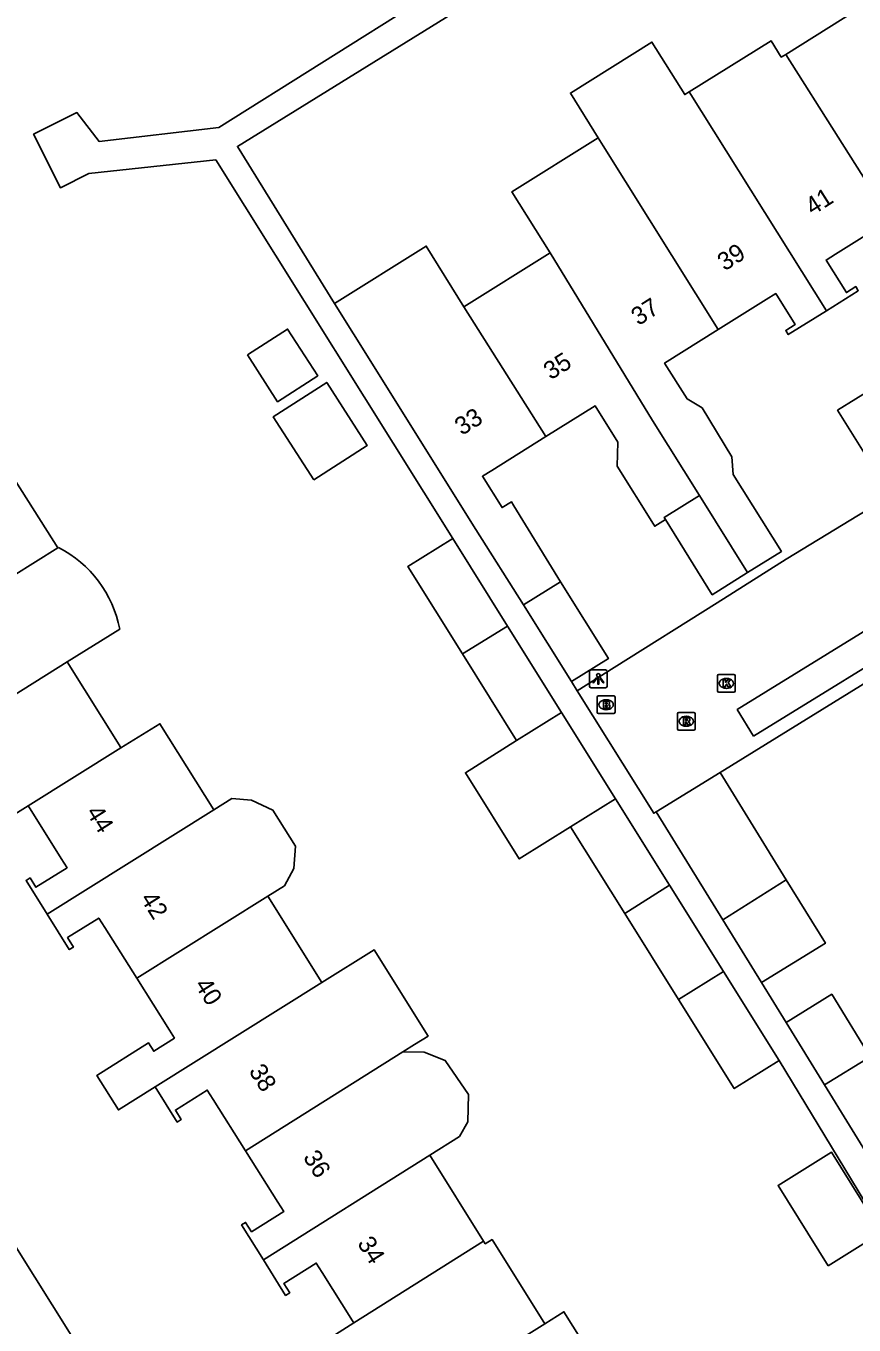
# Model space of a CAD drawing. Extents: x 157767 to 159171, y 387842 to 389425.
# Drawn here: x 158300.1 to 158346.5, y 388151.6 to 388224.4 of the extents above; entities that cross this region are included whole.
import ezdxf

# ---------------------------------------------------------------- set-up
doc = ezdxf.new("R2010")
doc.units = 0
for name, color, linetype in [('IMGEO_Brandkraan', 7, 'Continuous'), ('IMGEO_Kolk', 7, 'Continuous'), ('IMGEO_Lichtpunt', 7, 'Continuous'), ('IMGEO_Muur', 7, 'Continuous'), ('IMGEO_Pand', 7, 'Continuous'), ('IMGEO_Pand_nummerreeks', 7, 'Continuous'), ('IMGEO_Rijbaan_lokaal_open', 7, 'Continuous'), ('IMGEO_Rioolput', 7, 'Continuous'), ('IMGEO_Voetpad_open', 7, 'Continuous')]:
    doc.layers.add(name, color=color, linetype=linetype)

msp = doc.modelspace()

# ---------------------------------------------------------------- linework, layer by layer
at = {"layer": 'IMGEO_Brandkraan'}
for p, q in [((158332.146, 388185.961), (158332.146, 388186.813)), ((158332.221, 388186.887), (158333.073, 388186.887)), ((158332.634, 388186.667), (158332.659, 388186.667)), ((158333.147, 388186.813), (158333.147, 388185.961)), ((158333.073, 388185.887), (158332.221, 388185.887)), ((158332.657, 388186.107), (158332.632, 388186.107))]:
    msp.add_line(p, q, dxfattribs=at)
for points in [[(158332.146, 388185.961), (158332.146, 388186.813)], [(158332.221, 388186.887), (158333.073, 388186.887)], [(158332.494, 388186.587), (158332.494, 388186.187), (158332.707, 388186.187)], [(158332.725, 388186.587), (158332.494, 388186.587)], [(158332.673, 388186.506), (158332.619, 388186.506), (158332.619, 388186.43)], [(158332.619, 388186.43), (158332.672, 388186.43)], [(158332.681, 388186.354), (158332.619, 388186.354), (158332.619, 388186.273)], [(158333.147, 388186.813), (158333.147, 388185.961)], [(158333.073, 388185.887), (158332.221, 388185.887)], [(158332.619, 388186.273), (158332.681, 388186.273)]]:
    msp.add_lwpolyline(points, dxfattribs=at)
for centre, radius, start, end in [((158332.223, 388186.811), 0.0765, 91.55205, 178.44795), ((158332.223, 388186.811), 0.0765, 91.55205, 178.44795), ((158332.674, 388186.468), 0.0379, 267.82845, 90.93552), ((158332.682, 388186.313), 0.0404, 269.87594, 90.50774), ((158332.729, 388186.442), 0.145, 59.4692, 91.53667), ((158332.754, 388186.489), 0.0922, 285.51372, 58.15012), ((158332.759, 388186.297), 0.105, 301.31148, 78.98903), ((158333.071, 388186.811), 0.0765, 1.55205, 88.44795), ((158333.071, 388186.811), 0.0765, 1.55205, 88.44795), ((158332.223, 388185.963), 0.0765, 181.55205, 268.44795), ((158332.223, 388185.963), 0.0765, 181.55205, 268.44795), ((158332.713, 388186.438), 0.251, 268.66757, 293.53466), ((158333.071, 388185.963), 0.0765, 271.55205, 358.44795), ((158333.071, 388185.963), 0.0765, 271.55205, 358.44795)]:
    msp.add_arc(centre, radius, start, end, dxfattribs=at)
for centre, major_axis, ratio, start_param, end_param in [((158332.633, 388186.387), (-0.387, 0.002), 0.722429, 4.712389, 7.853982), ((158332.658, 388186.387), (-0.39, 0.002), 0.717154, 1.570796, 4.712389)]:
    msp.add_ellipse(centre, major_axis=major_axis, ratio=ratio, start_param=start_param, end_param=end_param, dxfattribs=at)
at = {"layer": 'IMGEO_Kolk'}
for p, q in [((158338.887, 388187.156), (158338.887, 388188.008)), ((158338.962, 388188.082), (158339.814, 388188.082)), ((158339.375, 388187.862), (158339.4, 388187.862)), ((158339.888, 388188.008), (158339.888, 388187.156)), ((158339.814, 388187.082), (158338.962, 388187.082)), ((158339.398, 388187.302), (158339.373, 388187.302))]:
    msp.add_line(p, q, dxfattribs=at)
for points in [[(158338.887, 388187.156), (158338.887, 388188.008)], [(158338.962, 388188.082), (158339.814, 388188.082)], [(158339.208, 388187.782), (158339.331, 388187.782), (158339.331, 388187.631), (158339.461, 388187.782), (158339.625, 388187.782), (158339.479, 388187.631), (158339.632, 388187.382), (158339.48, 388187.382), (158339.395, 388187.546), (158339.331, 388187.479), (158339.331, 388187.382), (158339.208, 388187.382), (158339.208, 388187.782)], [(158339.888, 388188.008), (158339.888, 388187.156)], [(158339.814, 388187.082), (158338.962, 388187.082)]]:
    msp.add_lwpolyline(points, dxfattribs=at)
for centre, start, end in [((158338.964, 388188.006), 91.55205, 178.44795), ((158338.964, 388188.006), 91.55205, 178.44795), ((158339.812, 388188.006), 1.55205, 88.44795), ((158339.812, 388188.006), 1.55205, 88.44795), ((158338.964, 388187.158), 181.55205, 268.44795), ((158338.964, 388187.158), 181.55205, 268.44795), ((158339.812, 388187.158), 271.55205, 358.44795), ((158339.812, 388187.158), 271.55205, 358.44795)]:
    msp.add_arc(centre, 0.0765, start, end, dxfattribs=at)
for centre, major_axis, ratio, start_param, end_param in [((158339.374, 388187.582), (-0.387, 0.002), 0.722429, 4.712389, 7.853982), ((158339.399, 388187.582), (-0.39, 0.002), 0.717154, 1.570796, 4.712389)]:
    msp.add_ellipse(centre, major_axis=major_axis, ratio=ratio, start_param=start_param, end_param=end_param, dxfattribs=at)
at = {"layer": 'IMGEO_Lichtpunt'}
for p, q in [((158331.71, 388188.236), (158331.71, 388187.429)), ((158331.71, 388188.236), (158331.71, 388187.429)), ((158332.612, 388188.331), (158331.804, 388188.331)), ((158332.612, 388188.331), (158331.804, 388188.331)), ((158332.706, 388187.429), (158332.706, 388188.236)), ((158332.706, 388187.429), (158332.706, 388188.236)), ((158331.804, 388187.335), (158332.612, 388187.335)), ((158331.804, 388187.335), (158332.612, 388187.335))]:
    msp.add_line(p, q, dxfattribs=at)
for points in [[(158332.084, 388187.9), (158332.123, 388187.872), (158331.935, 388187.61), (158331.897, 388187.637), (158332.084, 388187.9)], [(158332.186, 388187.852), (158332.233, 388187.852), (158332.233, 388187.53), (158332.186, 388187.53), (158332.186, 388187.852)], [(158332.296, 388187.872), (158332.334, 388187.899), (158332.521, 388187.637), (158332.482, 388187.609), (158332.296, 388187.872)]]:
    msp.add_lwpolyline(points, dxfattribs=at)
msp.add_circle((158332.209, 388188.034), 0.0994, dxfattribs=at)
for centre, start, end in [((158331.804, 388188.236), 90, 180), ((158331.804, 388188.236), 90, 180), ((158332.612, 388188.236), 0, 90), ((158332.612, 388188.236), 0, 90), ((158331.804, 388187.429), 180, 270), ((158331.804, 388187.429), 180, 270), ((158332.612, 388187.429), 270, 0), ((158332.612, 388187.429), 270, 360)]:
    msp.add_arc(centre, 0.0946, start, end, dxfattribs=at)
at = {"layer": 'IMGEO_Muur'}
msp.add_lwpolyline([(158352.615, 388190.965), (158339.034, 388182.597)], dxfattribs=at)
at = {"layer": 'IMGEO_Pand'}
for points in [[(158342.715, 388222.816), (158347.548, 388225.838)], [(158332.203, 388218.146), (158330.642, 388220.645), (158335.214, 388223.501), (158337.058, 388220.56), (158337.309, 388220.717)], [(158337.309, 388220.717), (158341.89, 388223.582), (158342.466, 388222.66), (158342.715, 388222.816)], [(158342.715, 388222.816), (158348.581, 388213.55)], [(158344.993, 388208.458), (158337.309, 388220.717)], [(158329.51, 388211.699), (158327.369, 388215.123), (158332.203, 388218.146)], [(158332.203, 388218.146), (158332.484, 388217.7), (158338.92, 388207.396)], [(158348.581, 388213.55), (158345.5, 388211.624), (158344.976, 388211.296), (158346.113, 388209.477), (158346.638, 388209.805), (158346.781, 388209.576), (158344.993, 388208.458)], [(158317.43, 388208.862), (158322.569, 388212.076), (158324.68, 388208.678)], [(158324.68, 388208.678), (158329.51, 388211.699)], [(158337.882, 388198.105), (158335.252, 388202.31), (158329.51, 388211.699)], [(158344.993, 388208.458), (158342.854, 388207.12), (158342.711, 388207.349), (158343.237, 388207.678), (158342.15, 388209.416), (158341.624, 388209.087), (158338.92, 388207.396)], [(158328.015, 388191.977), (158325.351, 388196.196), (158322.7, 388200.436), (158319.551, 388205.471), (158317.43, 388208.862)], [(158329.261, 388201.403), (158324.68, 388208.678)], [(158312.546, 388205.978), (158314.8, 388207.43), (158316.488, 388204.812), (158314.234, 388203.359), (158312.546, 388205.978)], [(158338.92, 388207.396), (158335.927, 388205.524), (158337.182, 388203.516), (158338.026, 388203.018), (158339.693, 388200.264), (158339.772, 388199.287), (158342.47, 388194.973), (158340.58, 388193.791)], [(158316.261, 388198.98), (158313.991, 388202.504), (158316.989, 388204.436), (158319.259, 388200.912), (158316.261, 388198.98)], [(158350.367, 388199.826), (158348.327, 388198.55), (158345.621, 388202.878), (158347.67, 388204.159)], [(158335.966, 388196.755), (158335.373, 388196.384), (158335.303, 388196.496), (158333.262, 388199.758), (158333.301, 388201.09), (158332.025, 388203.131), (158329.261, 388201.403)], [(158329.261, 388201.403), (158326.24, 388199.514), (158325.715, 388199.186), (158326.814, 388197.429), (158327.339, 388197.757), (158327.482, 388197.528), (158330.086, 388193.272)], [(158298.865, 388200.005), (158301.921, 388195.173)], [(158335.966, 388196.755), (158335.898, 388196.864), (158337.882, 388198.105)], [(158340.58, 388193.791), (158337.882, 388198.105)], [(158340.58, 388193.791), (158338.596, 388192.55), (158335.966, 388196.755)], [(158301.921, 388195.173), (158299.421, 388193.609), (158292.107, 388189.027)], [(158301.921, 388195.173), (158301.957, 388195.196)], [(158324.594, 388189.227), (158321.531, 388194.121), (158324.05, 388195.698)], [(158324.05, 388195.698), (158327.127, 388190.782)], [(158328.015, 388191.977), (158330.086, 388193.272)], [(158330.086, 388193.272), (158332.774, 388188.973), (158330.703, 388187.677)], [(158330.703, 388187.677), (158328.015, 388191.977)], [(158327.127, 388190.782), (158324.594, 388189.227)], [(158327.127, 388190.782), (158330.152, 388185.948)], [(158305.387, 388190.624), (158302.443, 388188.781)], [(158327.632, 388184.373), (158324.594, 388189.227)], [(158288.839, 388180.263), (158302.443, 388188.781)], [(158302.443, 388188.781), (158305.35, 388184.137), (158305.458, 388183.964)], [(158330.152, 388185.948), (158327.632, 388184.373)], [(158330.152, 388185.948), (158333.174, 388181.121)], [(158305.458, 388183.964), (158307.641, 388185.324), (158310.661, 388180.499)], [(158330.654, 388179.545), (158327.78, 388177.748), (158324.761, 388182.578), (158327.632, 388184.373)], [(158305.458, 388183.964), (158300.261, 388180.726)], [(158300.261, 388180.726), (158298.305, 388179.507), (158298.412, 388179.335), (158298.183, 388179.192), (158296.29, 388182.216), (158295.961, 388182.741), (158294.206, 388181.643), (158294.534, 388181.117), (158290.058, 388178.315), (158288.839, 388180.263)], [(158335.458, 388180.394), (158339.034, 388182.597)], [(158342.746, 388176.574), (158339.034, 388182.597)], [(158301.323, 388174.65), (158300.137, 388176.544), (158300.366, 388176.687), (158300.695, 388176.163), (158302.435, 388177.252), (158302.107, 388177.777), (158300.366, 388180.558), (158300.261, 388180.726)], [(158310.661, 388180.499), (158301.323, 388174.65)], [(158310.661, 388180.499), (158311.663, 388181.126), (158312.771, 388181.044), (158313.976, 388180.48), (158315.241, 388178.461), (158315.14, 388177.208), (158314.617, 388176.244), (158313.689, 388175.662)], [(158330.654, 388179.545), (158333.174, 388181.121)], [(158333.174, 388181.121), (158336.208, 388176.272)], [(158339.187, 388174.344), (158335.458, 388180.394)], [(158333.687, 388174.698), (158330.654, 388179.545)], [(158333.687, 388174.698), (158336.208, 388176.272)], [(158336.208, 388176.272), (158339.23, 388171.444)], [(158342.746, 388176.574), (158339.187, 388174.344)], [(158341.361, 388170.817), (158344.937, 388173.02), (158342.746, 388176.574)], [(158313.689, 388175.662), (158306.343, 388171.059)], [(158313.689, 388175.662), (158316.715, 388170.826)], [(158336.71, 388169.869), (158333.687, 388174.698)], [(158306.343, 388171.059), (158304.546, 388173.91), (158304.215, 388174.434), (158302.464, 388173.338), (158302.792, 388172.812), (158302.563, 388172.668), (158301.323, 388174.65)], [(158341.361, 388170.817), (158339.187, 388174.344)], [(158316.715, 388170.826), (158319.646, 388172.661), (158322.672, 388167.826), (158321.913, 388167.35), (158321.263, 388166.942)], [(158306.343, 388171.059), (158308.169, 388168.163), (158308.457, 388167.707), (158307.299, 388166.977), (158307.009, 388167.437), (158304.109, 388165.622), (158305.318, 388163.691), (158307.376, 388164.979)], [(158336.71, 388169.869), (158339.23, 388171.444)], [(158339.23, 388171.444), (158342.348, 388166.462)], [(158316.715, 388170.826), (158307.376, 388164.979)], [(158342.348, 388166.462), (158339.829, 388164.885), (158336.71, 388169.869)], [(158347.446, 388166.668), (158345.292, 388170.164), (158342.735, 388168.588)], [(158344.889, 388165.093), (158342.735, 388168.588)], [(158312.432, 388161.403), (158321.263, 388166.942)], [(158321.263, 388166.942), (158322.455, 388166.93), (158323.628, 388166.462), (158324.933, 388164.553), (158324.89, 388163.022), (158324.426, 388162.193), (158322.768, 388161.155)], [(158344.889, 388165.093), (158347.446, 388166.668)], [(158307.376, 388164.979), (158308.608, 388163.01), (158308.837, 388163.153), (158308.509, 388163.68), (158310.293, 388164.797), (158310.624, 388164.272), (158312.432, 388161.403)], [(158347.695, 388160.541), (158344.889, 388165.093)], [(158313.441, 388155.288), (158312.216, 388157.246), (158312.445, 388157.39), (158312.774, 388156.865), (158314.58, 388157.995), (158314.25, 388158.519), (158312.432, 388161.403)], [(158313.441, 388155.288), (158322.768, 388161.155)], [(158322.768, 388161.155), (158325.781, 388156.341)], [(158345.095, 388154.958), (158342.281, 388159.457), (158345.275, 388161.329), (158348.089, 388156.83), (158345.095, 388154.958)], [(158318.502, 388151.755), (158325.781, 388156.341)], [(158325.781, 388156.341), (158325.877, 388156.187), (158326.26, 388156.425), (158329.206, 388151.705)], [(158318.502, 388151.755), (158318.432, 388151.866), (158316.733, 388154.581), (158316.404, 388155.107), (158314.586, 388153.969), (158314.915, 388153.442), (158314.686, 388153.299), (158313.441, 388155.288)], [(158329.206, 388151.705), (158330.285, 388152.38), (158333.306, 388147.554), (158329.601, 388145.235)], [(158313.023, 388141.605), (158312.97, 388141.69), (158311.276, 388140.629), (158310.132, 388142.455), (158316.328, 388146.333), (158316.656, 388145.812), (158318.452, 388146.936), (158318.125, 388147.458), (158316.302, 388150.369), (158318.502, 388151.755)], [(158329.206, 388151.705), (158326.578, 388150.065), (158313.023, 388141.605)]]:
    msp.add_lwpolyline(points, dxfattribs=at)
msp.add_arc((158298.947, 388189.365), 6.562, 11.05977, 62.69607, dxfattribs=at)
at = {"layer": 'IMGEO_Rijbaan_lokaal_open'}
for points in [[(158331.025, 388187.169), (158333.092, 388188.466), (158338.88, 388192.098), (158342.746, 388194.533), (158348.606, 388198.107), (158352.487, 388200.522), (158355.385, 388202.255), (158355.501, 388202.324), (158354.496, 388203.976), (158373.677, 388216.222)], [(158339.034, 388182.597), (158352.615, 388190.965), (158365.167, 388198.706), (158381.815, 388172.081), (158383.379, 388169.579), (158383.764, 388168.963)], [(158340.911, 388184.618), (158339.992, 388186.111), (158360.492, 388198.747), (158361.412, 388197.254), (158340.911, 388184.618)], [(158335.458, 388180.394), (158335.32, 388180.308), (158331.025, 388187.169)]]:
    msp.add_lwpolyline(points, dxfattribs=at)
at = {"layer": 'IMGEO_Rioolput'}
for p, q in [((158336.64, 388185.03), (158336.64, 388185.882)), ((158336.715, 388185.956), (158337.567, 388185.956)), ((158337.128, 388185.736), (158337.153, 388185.736)), ((158337.641, 388185.882), (158337.641, 388185.03)), ((158337.567, 388184.956), (158336.715, 388184.956)), ((158337.151, 388185.176), (158337.126, 388185.176))]:
    msp.add_line(p, q, dxfattribs=at)
for points in [[(158336.64, 388185.03), (158336.64, 388185.882)], [(158336.715, 388185.956), (158337.567, 388185.956)], [(158337.229, 388185.654), (158336.977, 388185.656), (158336.977, 388185.256)], [(158337.641, 388185.882), (158337.641, 388185.03)], [(158337.567, 388184.956), (158336.715, 388184.956)], [(158336.977, 388185.256), (158337.101, 388185.256), (158337.101, 388185.418), (158337.112, 388185.418)], [(158337.155, 388185.575), (158337.101, 388185.575), (158337.101, 388185.494)], [(158337.101, 388185.494), (158337.153, 388185.494)], [(158337.159, 388185.389), (158337.23, 388185.256), (158337.37, 388185.256), (158337.305, 388185.382)]]:
    msp.add_lwpolyline(points, dxfattribs=at)
for centre, radius, start, end in [((158336.717, 388185.88), 0.0765, 91.55205, 178.44795), ((158336.717, 388185.88), 0.0765, 91.55205, 178.44795), ((158337.228, 388185.544), 0.109, 350.36119, 89.41601), ((158337.565, 388185.88), 0.0765, 1.55205, 88.44795), ((158337.565, 388185.88), 0.0765, 1.55205, 88.44795), ((158336.717, 388185.032), 0.0765, 181.55205, 268.44795), ((158336.717, 388185.032), 0.0765, 181.55205, 268.44795), ((158337.111, 388185.365), 0.0533, 26.02933, 88.69889), ((158337.137, 388185.683), 0.19, 274.7715, 282.96867), ((158337.161, 388185.479), 0.0964, 77.00612, 93.18647), ((158337.175, 388185.536), 0.0378, 276.66336, 79.67722), ((158337.226, 388185.544), 0.112, 277.58423, 350.98172), ((158337.21, 388185.329), 0.108, 29.51342, 73.79051), ((158337.565, 388185.032), 0.0765, 271.55205, 358.44795), ((158337.565, 388185.032), 0.0765, 271.55205, 358.44795)]:
    msp.add_arc(centre, radius, start, end, dxfattribs=at)
for centre, major_axis, ratio, start_param, end_param in [((158337.127, 388185.456), (-0.387, 0.002), 0.722429, 4.712389, 7.853982), ((158337.152, 388185.456), (-0.39, 0.002), 0.717154, 1.570796, 4.712389)]:
    msp.add_ellipse(centre, major_axis=major_axis, ratio=ratio, start_param=start_param, end_param=end_param, dxfattribs=at)
at = {"layer": 'IMGEO_Voetpad_open'}
for points in [[(158317.43, 388208.862), (158311.985, 388217.662), (158352.633, 388242.812)], [(158339.805, 388236.853), (158310.937, 388218.725), (158304.231, 388217.941), (158302.989, 388219.558), (158300.563, 388218.345), (158302.062, 388215.346), (158303.653, 388216.141), (158310.772, 388216.911), (158324.05, 388195.698)], [(158261.457, 388216.805), (158334.556, 388100.192)], [(158331.025, 388187.169), (158330.703, 388187.677)], [(158342.735, 388168.588), (158341.361, 388170.817)], [(158342.348, 388166.462), (158352.638, 388149.483), (158354.112, 388147.172)]]:
    msp.add_lwpolyline(points, dxfattribs=at)

# ---------------------------------------------------------------- texts
at = {"layer": 'IMGEO_Pand_nummerreeks'}
for s, rotation, p in [('41', 32.34104, (158344.215, 388213.768)), ('39', 32.34347, (158339.289, 388210.651)), ('37', 32.34104, (158334.459, 388207.591)), ('35', 32.01442, (158329.542, 388204.551)), ('33', 32.01442, (158324.563, 388201.438)), ('44', 302.19429, (158303.473, 388180.354)), ('42', 302.19492, (158306.512, 388175.528)), ('40', 302.19429, (158309.555, 388170.694)), ('38', 302.19429, (158312.595, 388165.865)), ('36', 302.19429, (158315.634, 388161.04)), ('34', 302.19429, (158318.674, 388156.211))]:
    msp.add_text(s, height=1, rotation=rotation, dxfattribs=at).set_placement(p)

doc.saveas('drawing.dxf')
